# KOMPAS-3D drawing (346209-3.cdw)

Referenced files in E:\Паша\Компас\Курсовая\: С1.cdw
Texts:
  КП.ОКМЧЕП.МЕ.12-00.000ВП
  Відомість курсового проекту
  Текст на чертеже
  Размерные надписи
  Шероховатость
  Линия-выноска #1
  Линия-выноска #2
  Линия-выноска #3
  Отклонения формы и база
  Заголовок таблицы
  Ячейка таблицы
  Стрелка вида
  Обозначение изменения
  Фигурная скобка
  Номер узла
  Марка координационной оси
  VRCB
  Выносная надпись
  Обозначение узла
  Марка/позиционное обозначение с линией-выноской
  Марка/позиционное обозначение на линии
  Марка/позиционное обозначение без линии-выноски
  КП.ОКМЧЕП.МЕ.12-00.000 ЗК
  Документація
  Завдання до КП
  Пояснювальна записка до КП
  КП.ОКМЧЕП.МЕ.12-02.000 СК
  КП.ОКМЧЕП.МЕ.12-02.000 СП
  Специфікація
  Привод конвеєра
  Стандартні вироби
  Манжети ГОСТ 8752-79
  Шарівський Я. В.
  Відомість курсового
  проекту
  Таран В. В.
  ПолтНТУ гр.301-МЕ
  КП.ОКМЧЕП.МЕ.11.01.000СП-
  КП.ОКМЧЕП.МЕ.12-00.000 ПЗ
  КП.ОКМЧЕП.МЕ.12-01.000 СК
  КП.ОКМЧЕП.МЕ.12-01.000 СП
  Редуктор циліндричний
Dimensions and other numbers on the sheet: 7; 4; 1:1; 1; 2009; 2; 30; 0; 3; 5; 6; 8; 9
